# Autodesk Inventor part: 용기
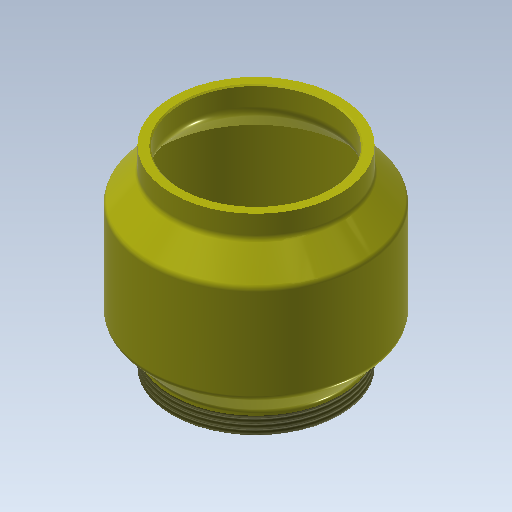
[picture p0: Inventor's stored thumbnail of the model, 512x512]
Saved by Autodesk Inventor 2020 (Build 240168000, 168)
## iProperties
Created: 2018-01
Part Number: 용기
Material: ABS 플라스틱
Document SubType Name: Modeling
Designer: mduedu
Density: 1 g/cm^3
Appearance: 노란색
Author: mduedu
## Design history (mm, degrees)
sketch "스케치1"
  geometry: L1 (0, 0)-(-35, 0); L2 (-35, 0)-(-35, 9); L3 (-35, 9)-(-45, 20); L4 (-45, 20)-(-45, 60); L5 (-45, 60)-(-35, 71); L6 (-35, 71)-(-35, 80); L7 (-35, 80)-(0, 80); L8 (0, 80)-(0, 0)
  constraints: 16 end point, 3 collinear, 3 parallel, 1 horizontal, 1 perpendicular
  dimensions: "d0" = 9 distance of L1.end L2.end; "d2" = 70 diameter of L2 L8; "d3" = 20 distance from line of L3.end L1; "d4" = 60 distance from line of L4.end L1; "d5" = 20 distance from line of L4.end L7; "d6" = 90 diameter of L4 L8
revolve "회전1" sketch "스케치1" stored, may be unused: angle "d7" = 90 deg
fillet "모깎기1" dims "d8" = 3
feature "쉘1" dims "d9" = 4
chamfer "모따기1" distance "d11" = 0.5; stored, may be unused: second distance "d12" = 2, angle "d13" = 45 deg
feature "스레드1" dims "d14" = 7, "d15" = 0
node "솔리드1"
